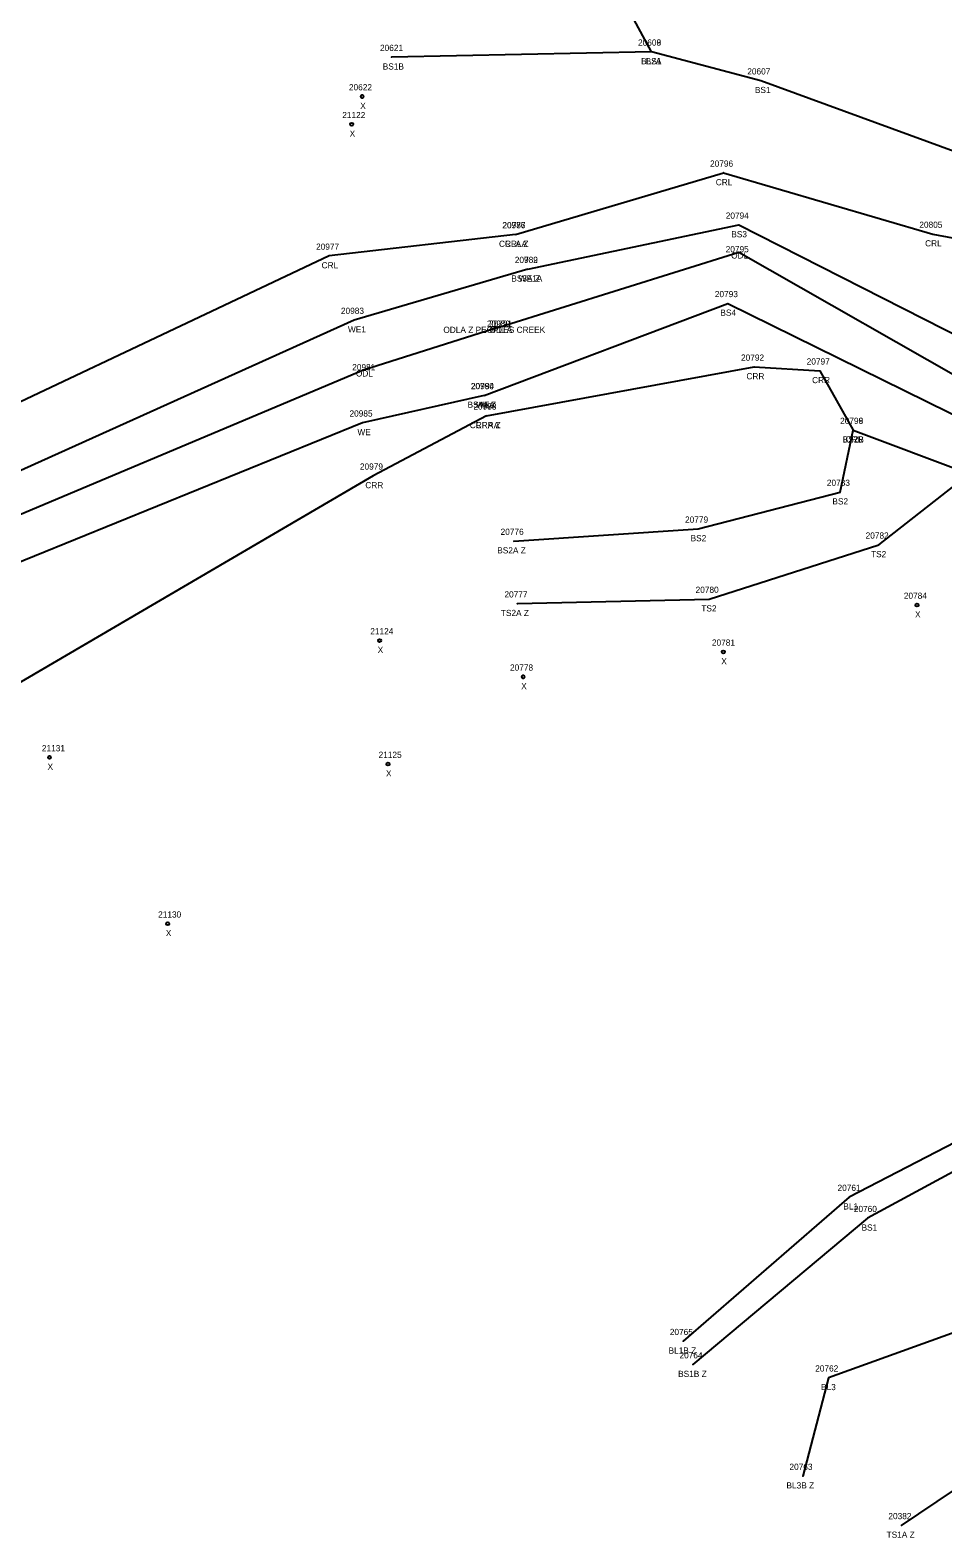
# Model space of a CAD drawing. Extents: x 1813127 to 1818290, y 1178171 to 1179900.
# Drawn here: x 1813421.4 to 1813568.5, y 1178496.2 to 1178739.3 of the extents above; entities that cross this region are included whole.
import ezdxf

# ---------------------------------------------------------------- set-up
doc = ezdxf.new("R2010")
doc.units = 0
for name, color, linetype in [('RD_DTM_BkLn1', 7, 'Continuous'), ('RD_DTM_BkLn2', 7, 'Continuous'), ('RD_EX_H2O', 7, 'Continuous'), ('RD_EX_H2O_txCode', 7, 'Continuous'), ('RD_SMD_Locator', 7, 'Continuous'), ('RD_SMD_Misc', 7, 'Continuous')]:
    doc.layers.add(name, color=color, linetype=linetype)

msp = doc.modelspace()

# ---------------------------------------------------------------- linework, layer by layer
at = {"layer": 'RD_DTM_BkLn1'}
for points in [[(1813521.54, 1178735.83), (1813516.61, 1178745.01), (1813509.8, 1178754.82), (1813493.76, 1178758.2), (1813445.29, 1178767.72), (1813423.54, 1178771.64)], [(1813684.91, 1178649.24), (1813672.9, 1178626.57), (1813636.59, 1178600.97), (1813597.02, 1178573.71), (1813553.38, 1178551.14), (1813526.62, 1178527.89)], [(1813683.38, 1178591.62), (1813653.58, 1178575.69), (1813601.65, 1178540.57), (1813550.07, 1178522.01), (1813545.91, 1178506.15)]]:
    msp.add_lwpolyline(points, dxfattribs=at)
at = {"layer": 'RD_DTM_BkLn2'}
for points in [[(1813501.61, 1178700.78), (1813535.62, 1178707.92), (1813578.65, 1178686.08), (1813588.2, 1178681.74), (1813622.61, 1178682.2), (1813653.79, 1178685.74), (1813685.17, 1178685.29), (1813723.1, 1178689.85), (1813736.83, 1178692.71), (1813771.26, 1178719.75), (1813784.46, 1178726.39), (1813801.14, 1178736.57), (1813819.08, 1178738.18), (1813840.25, 1178734.78), (1813848.44, 1178735.38), (1813862.15, 1178734.12), (1813885.61, 1178732.56), (1813903.34, 1178733.15)], [(1813719.9, 1178693.61), (1813672.18, 1178710.76), (1813660.65, 1178725.82), (1813637.51, 1178719.78), (1813596.2, 1178711.55), (1813573.69, 1178718.5), (1813539.15, 1178731.18), (1813521.54, 1178735.83), (1813479.61, 1178734.97)], [(1813494.55, 1178680.43), (1813533.86, 1178695.27), (1813573.03, 1178675.94), (1813630.33, 1178669.28), (1813656.92, 1178672.11), (1813691.39, 1178675.03), (1813721.31, 1178671.27), (1813738.7, 1178671.81), (1813780.2, 1178710.54), (1813805.93, 1178727.26), (1813819.91, 1178727.35), (1813841.4, 1178723.71), (1813860.66, 1178719.9), (1813869.89, 1178724.9), (1813872.35, 1178725.71), (1813884.47, 1178724.42), (1813903.61, 1178724.04)], [(1813499.34, 1178656.94), (1813529.06, 1178658.9), (1813551.92, 1178664.84), (1813554.06, 1178674.83)], [(1813499.93, 1178646.84), (1813530.8, 1178647.58), (1813558.17, 1178656.33), (1813572.78, 1178667.8)], [(1813687.73, 1178647.6), (1813673.94, 1178621.63), (1813639.04, 1178598.07), (1813598.95, 1178570.83), (1813556.33, 1178547.73), (1813528.18, 1178524.13)], [(1813561.84, 1178498.2), (1813604.88, 1178527.17), (1813645.67, 1178546.08), (1813692.97, 1178578.89), (1813742.95, 1178609.65)]]:
    msp.add_lwpolyline(points, dxfattribs=at)
at = {"layer": 'RD_EX_H2O'}
for points in [[(1813497.15, 1178691.5), (1813535.61, 1178703.5), (1813575.96, 1178680.52), (1813619.86, 1178677.62), (1813650.02, 1178676.71), (1813688.26, 1178680.15), (1813722.87, 1178676.67), (1813738.45, 1178684.24), (1813776.33, 1178715.9), (1813785.2, 1178724.07), (1813802.21, 1178734.6), (1813820.03, 1178732.78), (1813837.63, 1178729.78), (1813857.38, 1178730.32)], [(1813499.62, 1178706.37), (1813533.11, 1178716.31), (1813566.87, 1178706.45), (1813581.02, 1178703.79), (1813602.73, 1178697.66), (1813630.18, 1178688.94), (1813658.74, 1178690.22), (1813683.52, 1178690.56), (1813719.9, 1178693.61)], [(1813499.62, 1178706.37), (1813469.57, 1178702.91), (1813394.78, 1178667.56), (1813339.87, 1178627.25), (1813279.53, 1178636.34)], [(1813501.61, 1178700.78), (1813473.58, 1178692.57), (1813401.18, 1178659.94), (1813339.09, 1178617.63), (1813278.21, 1178629.52)], [(1813497.15, 1178691.5), (1813475.11, 1178684.47), (1813405.33, 1178655.15), (1813337.71, 1178611.7), (1813280.23, 1178623.46)], [(1813494.93, 1178677.14), (1813538.08, 1178685.02), (1813548.67, 1178684.4), (1813554.06, 1178674.83), (1813572.78, 1178667.8), (1813599.8, 1178663.18), (1813623.26, 1178662.12), (1813655.35, 1178662.6), (1813687.65, 1178668.53), (1813720.68, 1178667.78), (1813740.16, 1178669.89)], [(1813494.55, 1178680.43), (1813474.96, 1178676.01), (1813408.79, 1178649.13), (1813336.5, 1178605.02), (1813279.15, 1178618.81)], [(1813494.93, 1178677.14), (1813476.64, 1178667.45), (1813418.36, 1178633.33), (1813336.03, 1178599.49), (1813281.53, 1178610.55)]]:
    msp.add_lwpolyline(points, dxfattribs=at)
at = {"layer": 'RD_SMD_Locator'}
for centre, radius in [((1813521.54, 1178735.83), 0.001), ((1813521.54, 1178735.83), 0.001), ((1813479.61, 1178734.97), 0.001), ((1813539.15, 1178731.18), 0.001), ((1813474.89, 1178728.62), 0.25), ((1813473.19, 1178724.14), 0.25), ((1813533.11, 1178716.31), 0.001), ((1813499.62, 1178706.37), 0.001), ((1813499.62, 1178706.37), 0.001), ((1813535.62, 1178707.92), 0.001), ((1813566.87, 1178706.45), 0.001), ((1813469.57, 1178702.91), 0.001), ((1813535.61, 1178703.5), 0.001), ((1813501.61, 1178700.78), 0.001), ((1813501.61, 1178700.78), 0.001), ((1813533.86, 1178695.27), 0.001), ((1813473.58, 1178692.57), 0.001), ((1813497.15, 1178691.5), 0.001), ((1813497.15, 1178691.5), 0.001), ((1813475.11, 1178684.47), 0.001), ((1813538.08, 1178685.02), 0.001), ((1813548.67, 1178684.4), 0.001), ((1813494.55, 1178680.43), 0.001), ((1813494.55, 1178680.43), 0.001), ((1813494.93, 1178677.14), 0.001), ((1813494.93, 1178677.14), 0.001), ((1813474.96, 1178676.01), 0.001), ((1813554.06, 1178674.83), 0.001), ((1813554.06, 1178674.83), 0.001), ((1813476.64, 1178667.45), 0.001), ((1813551.92, 1178664.84), 0.001), ((1813529.06, 1178658.9), 0.001), ((1813499.34, 1178656.94), 0.001), ((1813558.17, 1178656.33), 0.001), ((1813499.93, 1178646.84), 0.001), ((1813530.8, 1178647.58), 0.001), ((1813564.33, 1178646.62), 0.25), ((1813477.7, 1178640.89), 0.25), ((1813533.1, 1178639.06), 0.25), ((1813500.84, 1178635.04), 0.25), ((1813424.47, 1178622.04), 0.25), ((1813479.04, 1178620.97), 0.25), ((1813443.54, 1178595.22), 0.25), ((1813553.38, 1178551.14), 0.001), ((1813556.33, 1178547.73), 0.001), ((1813526.62, 1178527.89), 0.001), ((1813528.18, 1178524.13), 0.001), ((1813550.07, 1178522.01), 0.001), ((1813545.91, 1178506.15), 0.001), ((1813561.84, 1178498.2), 0.001)]:
    msp.add_circle(centre, radius, dxfattribs=at)

# ---------------------------------------------------------------- texts
at = {"layer": 'RD_EX_H2O_txCode'}
for s, p in [('20796', (1813530.97, 1178717.31)), ('CRL', (1813531.89, 1178714.31)), ('20976', (1813497.47, 1178707.37)), ('20787', (1813497.5, 1178707.37)), ('20805', (1813564.71, 1178707.45)), ('20977', (1813467.45, 1178703.91)), ('CRLA Z', (1813496.94, 1178704.37)), ('CRLA', (1813497.9, 1178704.37)), ('20795', (1813533.49, 1178703.5)), ('CRL', (1813565.64, 1178704.45)), ('CRL', (1813468.34, 1178700.91)), ('20982', (1813499.49, 1178701.78)), ('ODL', (1813534.37, 1178702.5)), ('WE1A', (1813500.13, 1178698.78)), ('20983', (1813471.46, 1178693.57)), ('20980', (1813495, 1178691.5)), ('20791', (1813495.32, 1178691.5)), ('WE1', (1813472.59, 1178690.57)), ('ODLA Z PEOPLES CREEK', (1813487.97, 1178690.5)), ('ODLA', (1813495.42, 1178690.5)), ('20792', (1813535.96, 1178686.02)), ('20981', (1813473.28, 1178684.47)), ('ODL', (1813473.87, 1178683.47)), ('20797', (1813546.55, 1178685.4)), ('20984', (1813492.43, 1178681.43)), ('CRR', (1813536.83, 1178683.02)), ('CRR', (1813547.42, 1178682.4)), ('20985', (1813472.84, 1178677.01)), ('20788', (1813492.82, 1178678.14)), ('20978', (1813492.82, 1178678.14)), ('WEA', (1813493.24, 1178678.43)), ('WE', (1813474.12, 1178674.01)), ('CRRA Z', (1813492.23, 1178675.14)), ('CRRA', (1813493.19, 1178675.14)), ('20798', (1813551.94, 1178675.83)), ('CRR', (1813552.81, 1178672.83)), ('20979', (1813474.52, 1178668.45)), ('CRR', (1813475.39, 1178665.45))]:
    msp.add_text(s, height=1, dxfattribs=at).set_placement(p)
at = {"layer": 'RD_SMD_Misc'}
for s, p in [('20621', (1813477.76, 1178735.97)), ('20608', (1813519.36, 1178736.83)), ('20609', (1813519.36, 1178736.83)), ('BS1B', (1813478.2, 1178732.97)), ('BL2A', (1813519.85, 1178733.83)), ('BS1', (1813520.59, 1178733.83)), ('20607', (1813536.97, 1178732.18)), ('20622', (1813472.75, 1178729.62)), ('BS1', (1813538.2, 1178729.18)), ('21122', (1813471.67, 1178725.14)), ('X', (1813474.57, 1178726.62)), ('X', (1813472.87, 1178722.14)), ('20794', (1813533.5, 1178708.92)), ('BS3', (1813534.39, 1178705.92)), ('20789', (1813499.49, 1178701.78)), ('BS3A Z', (1813498.93, 1178698.78)), ('20793', (1813531.74, 1178696.27)), ('BS4', (1813532.63, 1178693.27)), ('20790', (1813492.39, 1178681.43)), ('BS4A Z', (1813491.87, 1178678.43)), ('20799', (1813551.94, 1178675.83)), ('BS2B', (1813552.36, 1178672.83)), ('20783', (1813549.8, 1178665.84)), ('BS2', (1813550.69, 1178662.84)), ('20779', (1813526.94, 1178659.9)), ('20776', (1813497.2, 1178657.94)), ('BS2', (1813527.83, 1178656.9)), ('20782', (1813556.05, 1178657.33)), ('BS2A Z', (1813496.66, 1178654.94)), ('TS2', (1813556.92, 1178654.33)), ('20777', (1813497.82, 1178647.84)), ('20780', (1813528.64, 1178648.58)), ('20784', (1813562.21, 1178647.62)), ('TS2A Z', (1813497.24, 1178644.84)), ('TS2', (1813529.56, 1178645.58)), ('X', (1813564.02, 1178644.62)), ('21124', (1813476.19, 1178641.89)), ('20781', (1813531.27, 1178640.06)), ('X', (1813477.38, 1178638.89)), ('20778', (1813498.72, 1178636.04)), ('X', (1813532.78, 1178637.06)), ('X', (1813500.52, 1178633.04)), ('21131', (1813423.25, 1178623.04)), ('21125', (1813477.53, 1178621.97)), ('X', (1813424.16, 1178620.04)), ('X', (1813478.72, 1178618.97)), ('21130', (1813441.99, 1178596.22)), ('X', (1813443.23, 1178593.22)), ('20761', (1813551.52, 1178552.14)), ('BL1', (1813552.46, 1178549.14)), ('20760', (1813554.15, 1178548.73)), ('BS1', (1813555.39, 1178545.73)), ('20765', (1813524.48, 1178528.89)), ('BL1B Z', (1813524.28, 1178525.89)), ('20764', (1813526.04, 1178525.13)), ('20762', (1813547.92, 1178523.01)), ('BS1B Z', (1813525.82, 1178522.13)), ('BL3', (1813548.86, 1178520.01)), ('20763', (1813543.77, 1178507.15)), ('BL3B Z', (1813543.29, 1178504.15)), ('20382', (1813559.72, 1178499.2)), ('TS1A Z', (1813559.43, 1178496.2))]:
    msp.add_text(s, height=1, dxfattribs=at).set_placement(p)

doc.saveas('drawing.dxf')
